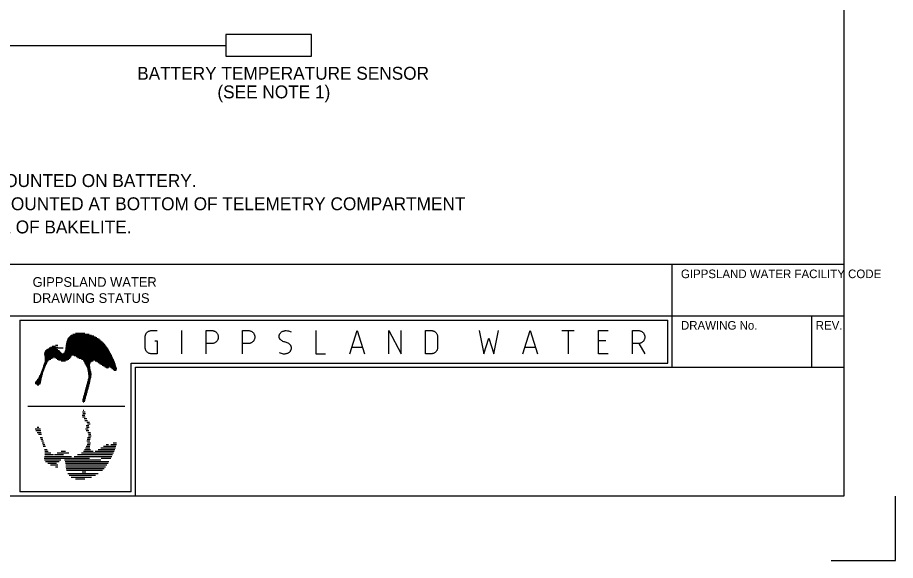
# Model space of a CAD drawing. Extents: x 0 to 841, y 0 to 594.
# Drawn here: x 636.5 to 841, y 0 to 126.5 of the extents above; entities that cross this region are included whole.
import ezdxf

# ---------------------------------------------------------------- set-up
doc = ezdxf.new("R2010")
doc.units = 0
doc.layers.add('A1BORDER', color=7, linetype='Continuous')
doc.layers.add('Level 1', color=7, linetype='Continuous')

msp = doc.modelspace()

# ---------------------------------------------------------------- linework, layer by layer
at = {"layer": 'A1BORDER'}
for p, q in [((829, 581), (829, 15)), ((592.5, 69), (829, 69)), ((789, 45), (789, 69)), ((28, 57), (829, 57)), ((637, 56), (788, 56)), ((637, 56), (637, 16)), ((788, 46), (788, 56)), ((821.5, 45), (821.5, 57)), ((648.03, 51.32), (655.85, 51.32)), ((648.12, 51.52), (655.59, 51.52)), ((648.23, 51.72), (655.31, 51.72)), ((648.37, 51.92), (655, 51.92)), ((648.53, 52.12), (654.64, 52.12)), ((648.74, 52.32), (654.24, 52.32)), ((649.02, 52.52), (653.76, 52.52)), ((649.39, 52.72), (653.15, 52.72)), ((650.01, 52.92), (652.2, 52.92)), ((643.26, 49.12), (645.9, 49.12)), ((643.54, 49.32), (645.57, 49.32)), ((643.85, 49.52), (647.09, 49.52)), ((644.18, 49.72), (645.89, 49.72)), ((644.54, 49.92), (645.36, 49.92)), ((645.37, 50.12), (645.86, 50.12)), ((647.63, 49.12), (657.68, 49.12)), ((647.66, 49.32), (657.57, 49.32)), ((647.69, 49.52), (657.44, 49.52)), ((647.71, 49.72), (657.31, 49.72)), ((647.75, 49.92), (657.17, 49.92)), ((647.78, 50.12), (657.02, 50.12)), ((647.81, 50.32), (656.86, 50.32)), ((647.85, 50.52), (656.69, 50.52)), ((647.88, 50.72), (656.5, 50.72)), ((647.91, 50.92), (656.3, 50.92)), ((647.96, 51.12), (656.08, 51.12)), ((642.73, 48.12), (658.25, 48.12)), ((642.74, 47.92), (658.35, 47.92)), ((642.75, 48.32), (646.79, 48.32)), ((642.79, 47.72), (649.08, 47.72)), ((642.81, 48.52), (646.55, 48.52)), ((642.83, 47.52), (648.95, 47.52)), ((642.85, 47.31), (644.88, 47.31)), ((642.87, 47.12), (644.57, 47.12)), ((642.9, 48.72), (646.37, 48.72)), ((643.04, 48.92), (646.16, 48.92)), ((645.14, 47.31), (648.83, 47.31)), ((645.49, 47.12), (648.67, 47.12)), ((647.19, 48.32), (658.14, 48.32)), ((647.42, 48.52), (658.03, 48.52)), ((647.54, 48.72), (657.92, 48.72)), ((647.61, 48.92), (657.8, 48.92)), ((649.72, 47.72), (658.45, 47.72)), ((650.12, 47.52), (658.55, 47.52)), ((650.48, 47.31), (658.64, 47.31)), ((650.87, 47.12), (658.73, 47.12)), ((642.43, 45.12), (642.9, 45.12)), ((642.5, 45.32), (643, 45.32)), ((642.57, 45.52), (643.1, 45.52)), ((642.65, 45.72), (643.2, 45.72)), ((642.72, 45.92), (643.3, 45.92)), ((642.79, 46.12), (643.4, 46.12)), ((642.84, 46.32), (643.5, 46.32)), ((642.87, 46.52), (643.6, 46.52)), ((642.88, 46.92), (644.23, 46.92)), ((642.88, 46.72), (643.83, 46.72)), ((645.76, 46.92), (648.42, 46.92)), ((646.05, 46.72), (648.11, 46.72)), ((646.62, 46.52), (647.67, 46.52)), ((651.36, 46.92), (658.82, 46.92)), ((651.76, 46.72), (658.9, 46.72)), ((651.88, 46.52), (654.15, 46.52)), ((651.99, 46.32), (653.71, 46.32)), ((652.1, 46.12), (653.52, 46.12)), ((652.2, 45.92), (653.4, 45.92)), ((652.31, 45.72), (653.33, 45.72)), ((652.41, 45.52), (653.31, 45.52)), ((652.5, 45.32), (653.34, 45.32)), ((652.6, 45.12), (653.38, 45.12)), ((654.57, 46.52), (658.99, 46.52)), ((655, 46.32), (659.07, 46.32)), ((655.31, 46.12), (659.14, 46.12)), ((655.62, 45.92), (659.22, 45.92)), ((655.93, 45.72), (659.29, 45.72)), ((656.24, 45.52), (659.35, 45.52)), ((656.55, 45.32), (659.42, 45.32)), ((656.86, 45.12), (657.74, 45.12)), ((657.91, 45.12), (659.48, 45.12)), ((663, 46), (788, 46)), ((663, 16), (663, 46)), ((664, 45), (829, 45)), ((664, 15), (664, 45)), ((641.64, 43.12), (642.25, 43.12)), ((641.73, 43.32), (642.3, 43.32)), ((641.82, 43.51), (642.35, 43.51)), ((641.91, 43.72), (642.41, 43.72)), ((641.99, 43.92), (642.48, 43.92)), ((642.06, 44.12), (642.55, 44.12)), ((642.13, 44.32), (642.62, 44.32)), ((642.21, 44.52), (642.69, 44.52)), ((642.28, 44.72), (642.76, 44.72)), ((642.35, 44.92), (642.83, 44.92)), ((652.69, 44.92), (653.41, 44.92)), ((652.78, 44.72), (653.44, 44.72)), ((652.83, 44.52), (653.48, 44.52)), ((652.86, 44.32), (653.53, 44.32)), ((652.89, 44.12), (653.57, 44.12)), ((652.91, 43.92), (653.62, 43.92)), ((652.94, 43.72), (653.67, 43.72)), ((652.97, 43.51), (653.71, 43.51)), ((653, 43.32), (653.69, 43.32)), ((653.02, 43.12), (653.67, 43.12)), ((657.17, 44.92), (657.68, 44.92)), ((657.51, 44.72), (657.54, 44.72)), ((658.19, 44.92), (659.54, 44.92)), ((658.47, 44.72), (659.59, 44.72)), ((658.75, 44.52), (659.58, 44.52)), ((659.02, 44.32), (659.47, 44.32)), ((640.62, 41.32), (641.88, 41.32)), ((640.63, 41.52), (641.93, 41.52)), ((640.72, 41.12), (641.73, 41.12)), ((640.73, 41.72), (641.95, 41.72)), ((640.9, 41.92), (641.97, 41.92)), ((641.03, 40.92), (641.43, 40.92)), ((641.1, 42.12), (642, 42.12)), ((641.25, 42.31), (642.04, 42.31)), ((641.37, 42.52), (642.09, 42.52)), ((641.46, 42.72), (642.15, 42.72)), ((641.55, 42.92), (642.2, 42.92)), ((652.57, 40.92), (653.2, 40.92)), ((652.63, 41.12), (653.26, 41.12)), ((652.68, 41.32), (653.31, 41.32)), ((652.74, 41.52), (653.37, 41.52)), ((652.79, 41.72), (653.41, 41.72)), ((652.85, 41.92), (653.45, 41.92)), ((652.9, 42.12), (653.49, 42.12)), ((652.95, 42.31), (653.53, 42.31)), ((652.99, 42.52), (653.57, 42.52)), ((653.03, 42.72), (653.61, 42.72)), ((653.05, 42.92), (653.64, 42.92)), ((652.03, 38.92), (652.66, 38.92)), ((652.09, 39.12), (652.72, 39.12)), ((652.14, 39.32), (652.77, 39.32)), ((652.2, 39.52), (652.82, 39.52)), ((652.25, 39.72), (652.88, 39.72)), ((652.3, 39.92), (652.93, 39.92)), ((652.36, 40.12), (652.99, 40.12)), ((652.41, 40.32), (653.04, 40.32)), ((652.47, 40.52), (653.1, 40.52)), ((652.52, 40.72), (653.15, 40.72)), ((651.63, 37.32), (652.23, 37.32)), ((651.64, 37.12), (652.17, 37.12)), ((651.65, 37.52), (652.28, 37.52)), ((651.71, 37.72), (652.34, 37.72)), ((651.76, 37.92), (652.39, 37.92)), ((651.79, 36.92), (651.9, 36.92)), ((651.82, 38.12), (652.44, 38.12)), ((651.87, 38.32), (652.5, 38.32)), ((651.92, 38.52), (652.55, 38.52)), ((651.98, 38.72), (652.61, 38.72)), ((638.93, 35.98), (661.47, 35.98)), ((651.79, 35.04), (651.9, 35.04)), ((651.54, 33.84), (652.17, 33.84)), ((651.63, 34.64), (652.23, 34.64)), ((651.65, 33.44), (652.28, 33.44)), ((651.71, 34.24), (652.34, 34.24)), ((652.03, 33.04), (652.66, 33.04)), ((641.03, 31.04), (641.43, 31.04)), ((652.14, 32.64), (652.77, 32.64)), ((652.47, 31.44), (653.1, 31.44)), ((652.57, 31.04), (653.2, 31.04)), ((652.66, 32.24), (653.29, 32.24)), ((652.77, 31.84), (653.4, 31.84)), ((640.62, 30.64), (641.88, 30.64)), ((640.73, 30.24), (641.95, 30.24)), ((641.1, 29.84), (642, 29.84)), ((641.37, 29.44), (642.09, 29.44)), ((641.73, 28.64), (642.3, 28.64)), ((652.34, 30.64), (652.97, 30.64)), ((652.45, 30.24), (653.07, 30.24)), ((652.77, 28.64), (653.46, 28.64)), ((652.9, 29.84), (653.49, 29.84)), ((652.99, 29.44), (653.57, 29.44)), ((653.05, 29.04), (653.64, 29.04)), ((641.91, 28.24), (642.41, 28.24)), ((642.06, 27.84), (642.55, 27.84)), ((642.21, 27.44), (642.69, 27.44)), ((642.35, 27.04), (642.83, 27.04)), ((642.5, 26.64), (643, 26.64)), ((652.5, 26.64), (653.34, 26.64)), ((652.66, 27.84), (653.35, 27.84)), ((652.69, 27.04), (653.41, 27.04)), ((652.72, 28.24), (653.44, 28.24)), ((652.83, 27.44), (653.48, 27.44)), ((656.55, 26.64), (659.42, 26.64)), ((657.17, 27.04), (657.68, 27.04)), ((658.19, 27.04), (659.54, 27.04)), ((658.75, 27.44), (659.58, 27.44)), ((642.79, 25.84), (643.4, 25.84)), ((642.85, 24.65), (644.88, 24.65)), ((642.87, 25.44), (643.6, 25.44)), ((642.88, 25.04), (644.23, 25.04)), ((645.14, 24.65), (647.18, 24.65)), ((645.76, 25.04), (648.42, 25.04)), ((646.62, 25.44), (647.67, 25.44)), ((650.48, 24.65), (658.64, 24.65)), ((651.36, 25.04), (658.82, 25.04)), ((651.88, 25.44), (654.15, 25.44)), ((652.1, 25.84), (653.52, 25.84)), ((652.31, 26.24), (653.33, 26.24)), ((654.57, 25.44), (658.99, 25.44)), ((655.31, 25.84), (659.14, 25.84)), ((655.93, 26.24), (659.29, 26.24)), ((642.73, 23.84), (653.27, 23.84)), ((642.79, 24.24), (649.08, 24.24)), ((642.81, 23.44), (646.55, 23.44)), ((643.04, 23.04), (646.16, 23.04)), ((643.54, 22.64), (645.57, 22.64)), ((647.42, 23.44), (655.89, 23.44)), ((647.61, 23.04), (657.8, 23.04)), ((647.66, 22.64), (657.57, 22.64)), ((649.72, 24.24), (658.45, 24.24)), ((655.94, 23.84), (658.25, 23.84)), ((644.18, 22.24), (645.89, 22.24)), ((645.37, 21.84), (645.86, 21.84)), ((647.71, 22.24), (657.31, 22.24)), ((647.78, 21.84), (657.02, 21.84)), ((647.85, 21.44), (656.69, 21.44)), ((647.91, 21.04), (656.3, 21.04)), ((651.57, 20.64), (652.44, 20.64)), ((648.23, 20.24), (655.31, 20.24)), ((648.53, 19.84), (654.64, 19.84)), ((649.02, 19.44), (653.76, 19.44)), ((650.01, 19.04), (652.2, 19.04)), ((829, 15), (28, 15)), ((663, 16), (637, 16)), ((829, 15), (829, 15)), ((841, 0), (841, 15)), ((826, 0), (841, 0))]:
    msp.add_line(p, q, dxfattribs=at)
for points in [[(668.49, 51.15), (669.06, 51.15), (669.06, 48.16), (667.64, 48.16), (667.51, 48.16), (667.39, 48.18), (667.28, 48.21), (667.15, 48.25), (667.04, 48.3), (666.93, 48.36), (666.82, 48.43), (666.73, 48.51), (666.64, 48.6), (666.55, 48.7), (666.48, 48.8), (666.41, 48.91), (666.35, 49.02), (666.31, 49.14), (666.27, 49.27), (666.24, 49.39), (666.22, 49.52), (666.22, 49.66), (666.22, 52.05), (666.22, 52.18), (666.24, 52.31), (666.27, 52.43), (666.31, 52.56), (666.35, 52.67), (666.41, 52.79), (666.48, 52.9), (666.55, 53), (666.64, 53.1), (666.73, 53.19), (666.82, 53.27), (666.93, 53.34), (667.04, 53.4), (667.15, 53.45), (667.28, 53.49), (667.39, 53.52), (667.51, 53.54), (667.64, 53.54), (669.06, 53.54)], [(674.74, 48.16), (674.74, 53.54)], [(680.42, 48.16), (680.42, 53.54), (681.84, 53.54), (681.96, 53.54), (682.08, 53.52), (682.2, 53.49), (682.32, 53.45), (682.43, 53.4), (682.54, 53.34), (682.65, 53.27), (682.74, 53.19), (682.84, 53.1), (682.92, 53), (682.99, 52.9), (683.06, 52.79), (683.12, 52.67), (683.17, 52.56), (683.21, 52.43), (683.23, 52.31), (683.25, 52.18), (683.26, 52.05), (683.25, 51.91), (683.23, 51.78), (683.21, 51.66), (683.17, 51.53), (683.12, 51.42), (683.06, 51.3), (682.99, 51.19), (682.92, 51.09), (682.84, 50.99), (682.74, 50.9), (682.65, 50.82), (682.54, 50.75), (682.43, 50.69), (682.32, 50.64), (682.2, 50.6), (682.08, 50.57), (681.96, 50.55), (681.84, 50.55), (680.42, 50.55)], [(688.93, 48.16), (688.93, 53.54), (690.35, 53.54), (690.47, 53.54), (690.59, 53.52), (690.71, 53.49), (690.83, 53.45), (690.94, 53.4), (691.05, 53.34), (691.16, 53.27), (691.26, 53.19), (691.35, 53.1), (691.43, 53), (691.51, 52.9), (691.57, 52.79), (691.63, 52.67), (691.68, 52.56), (691.72, 52.43), (691.75, 52.31), (691.76, 52.18), (691.77, 52.05), (691.76, 51.91), (691.75, 51.78), (691.72, 51.66), (691.68, 51.53), (691.63, 51.42), (691.57, 51.3), (691.51, 51.19), (691.43, 51.09), (691.35, 50.99), (691.26, 50.9), (691.16, 50.82), (691.05, 50.75), (690.94, 50.69), (690.83, 50.64), (690.71, 50.6), (690.59, 50.57), (690.47, 50.55), (690.35, 50.55), (688.93, 50.55)], [(697.45, 48.46), (697.67, 48.36), (697.9, 48.27), (698.12, 48.21), (698.36, 48.17), (698.6, 48.16), (698.84, 48.16), (698.87, 48.16), (699.03, 48.18), (699.18, 48.21), (699.33, 48.26), (699.48, 48.32), (699.62, 48.4), (699.72, 48.46), (699.81, 48.53), (699.9, 48.61), (699.98, 48.69), (700.05, 48.78), (700.11, 48.88), (700.17, 48.99), (700.22, 49.09), (700.25, 49.21), (700.28, 49.32), (700.29, 49.36), (700.3, 49.44), (700.3, 49.52), (700.3, 49.61), (700.29, 49.69), (700.27, 49.77), (700.25, 49.86), (700.22, 49.93), (700.18, 50.01), (700.14, 50.09), (700.09, 50.15), (700.04, 50.21), (700.01, 50.25), (699.85, 50.39), (699.69, 50.51), (699.52, 50.61), (699.34, 50.7), (699.15, 50.78), (698.95, 50.83), (698.87, 50.85), (698.68, 50.9), (698.49, 50.96), (698.3, 51.04), (698.12, 51.14), (697.96, 51.26), (697.8, 51.39), (697.73, 51.45), (697.67, 51.51), (697.62, 51.57), (697.58, 51.64), (697.53, 51.71), (697.5, 51.79), (697.47, 51.87), (697.46, 51.95), (697.44, 52.04), (697.43, 52.12), (697.43, 52.21), (697.44, 52.29), (697.45, 52.35), (697.47, 52.46), (697.51, 52.58), (697.55, 52.69), (697.61, 52.79), (697.67, 52.89), (697.74, 52.99), (697.82, 53.07), (697.9, 53.15), (697.99, 53.23), (698.02, 53.24), (698.15, 53.33), (698.3, 53.4), (698.44, 53.45), (698.6, 53.5), (698.75, 53.52), (698.87, 53.54), (699.11, 53.55), (699.35, 53.53), (699.58, 53.49), (699.82, 53.43), (700.04, 53.35), (700.27, 53.25)], [(705.96, 53.54), (705.96, 48.16), (708.23, 48.16)], [(713.91, 48.16), (715.61, 53.54), (717.32, 48.16)], [(722.99, 48.16), (722.99, 53.54), (725.83, 48.16), (725.83, 53.54)], [(731.52, 48.16), (731.52, 53.54), (732.94, 53.54), (733.06, 53.54), (733.18, 53.52), (733.3, 53.49), (733.42, 53.45), (733.53, 53.4), (733.64, 53.34), (733.75, 53.27), (733.84, 53.19), (733.94, 53.1), (734.02, 53), (734.09, 52.9), (734.16, 52.79), (734.22, 52.67), (734.27, 52.56), (734.31, 52.43), (734.33, 52.31), (734.35, 52.18), (734.36, 52.05), (734.36, 49.66), (734.35, 49.52), (734.33, 49.39), (734.31, 49.27), (734.27, 49.14), (734.22, 49.02), (734.16, 48.91), (734.09, 48.8), (734.02, 48.7), (733.94, 48.6), (733.84, 48.51), (733.75, 48.43), (733.64, 48.36), (733.53, 48.3), (733.42, 48.25), (733.3, 48.21), (733.18, 48.18), (733.06, 48.16), (732.94, 48.16), (731.52, 48.16)], [(744.01, 53.54), (745.14, 48.16), (746.28, 51.75), (747.41, 48.16), (748.55, 53.54)], [(754.22, 48.16), (755.92, 53.54), (757.63, 48.16)], [(763.31, 53.54), (766.15, 53.54)], [(764.73, 53.54), (764.73, 48.16)], [(774.09, 48.16), (771.82, 48.16), (771.82, 53.54), (774.09, 53.54)], [(779.78, 48.16), (779.78, 53.54), (781.2, 53.54), (781.32, 53.54), (781.44, 53.52), (781.56, 53.49), (781.68, 53.45), (781.79, 53.4), (781.9, 53.34), (782.01, 53.27), (782.1, 53.19), (782.2, 53.1), (782.28, 53), (782.35, 52.9), (782.42, 52.79), (782.48, 52.67), (782.53, 52.56), (782.56, 52.43), (782.59, 52.31), (782.61, 52.18), (782.61, 52.05), (782.61, 51.91), (782.59, 51.78), (782.56, 51.66), (782.53, 51.53), (782.48, 51.42), (782.42, 51.3), (782.35, 51.19), (782.28, 51.09), (782.2, 50.99), (782.1, 50.9), (782.01, 50.82), (781.9, 50.75), (781.79, 50.69), (781.68, 50.64), (781.56, 50.6), (781.44, 50.57), (781.32, 50.55), (781.2, 50.55), (779.78, 50.55)], [(773.53, 51.15), (771.82, 51.15)], [(714.48, 49.66), (716.75, 49.66)], [(754.79, 49.66), (757.06, 49.66)], [(781.2, 50.55), (782.61, 48.16)]]:
    msp.add_lwpolyline(points, dxfattribs=at)
at = {"layer": 'Level 1'}
msp.add_line((255, 120), (685, 120), dxfattribs=at)
msp.add_lwpolyline([(685, 117.5), (705, 117.5), (705, 122.5), (685, 122.5)], close=True, dxfattribs=at)

# ---------------------------------------------------------------- texts
at = {"layer": 'A1BORDER'}
for s, height, p in [('GIPPSLAND WATER FACILITY CODE', 2, (791.03, 65.77)), ('GIPPSLAND WATER', 2.25, (640, 63.75)), ('DRAWING STATUS', 2.25, (640, 60)), ('DRAWING No.', 2, (791.03, 53.77)), ('REV.', 2, (822.43, 53.77))]:
    msp.add_text(s, height=height, dxfattribs=at).set_placement(p)
at = {"layer": 'Level 1'}
for s, p in [('BATTERY TEMPERATURE SENSOR', (664.37, 112)), ('(SEE NOTE 1)', (683.05, 107.66)), ('SENSOR MOUNTED ON BATTERY.', (612, 87)), ('BATTERY MOUNTED AT BOTTOM OF TELEMETRY COMPARTMENT', (612, 81.6)), ('ON A PIECE OF BAKELITE.', (612, 76.2))]:
    msp.add_text(s, height=3, dxfattribs=at).set_placement(p)

doc.saveas('drawing.dxf')
